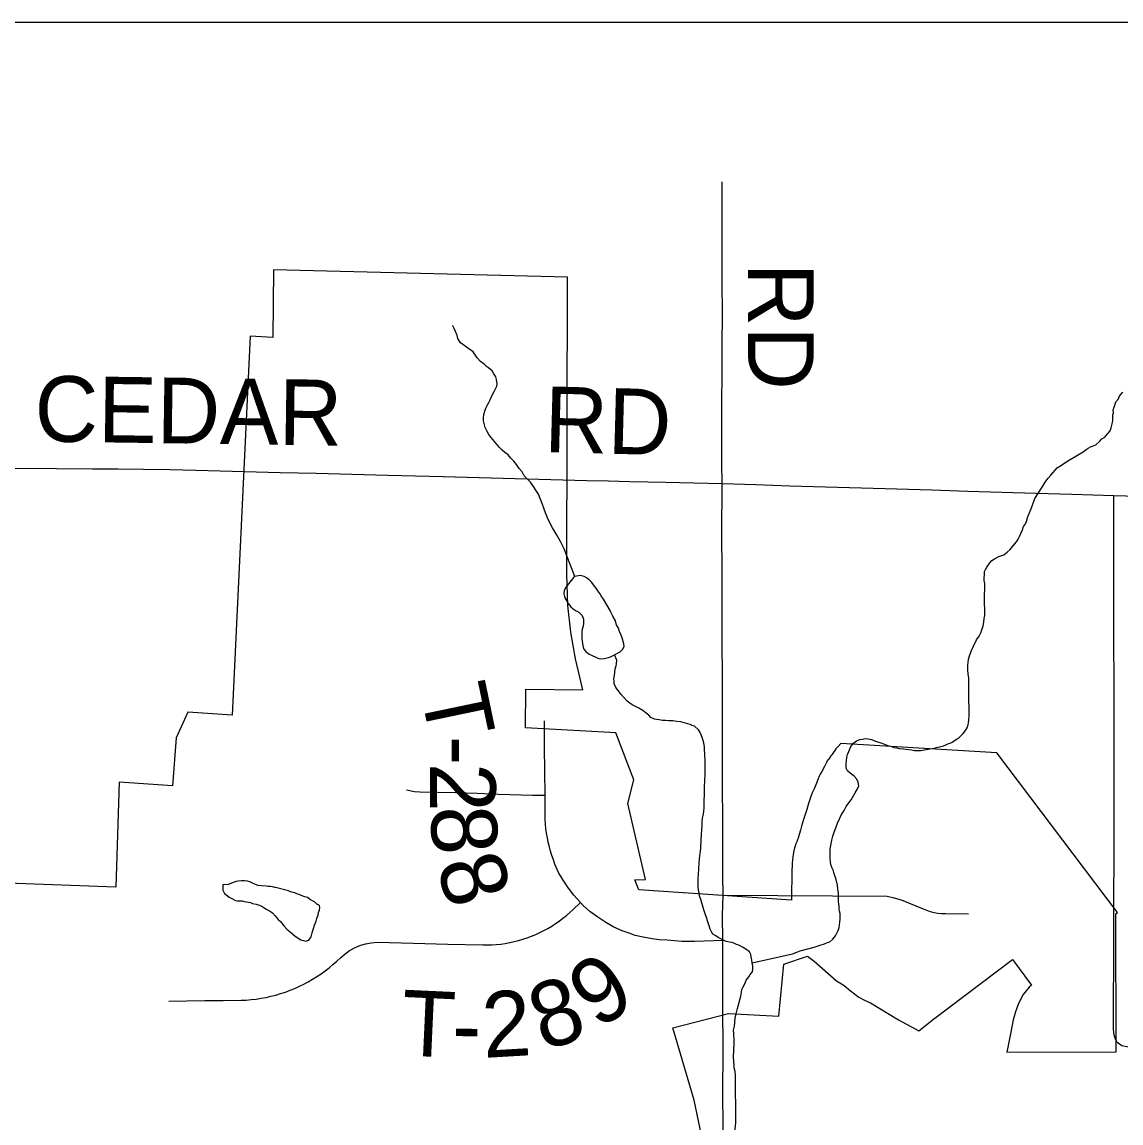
# Model space of a CAD drawing. Extents: x -11.4 to 84.1, y 11.1 to 59.
# Drawn here: x 26.686 to 27.637, y 46.596 to 47.548 of the extents above; entities that cross this region are included whole.
import ezdxf

# ---------------------------------------------------------------- set-up
doc = ezdxf.new("R2010")
doc.units = 0
for name, color, linetype in [('GM_X_Corporation', 7, 'Continuous'), ('GM_X_County_Road', 7, 'Continuous'), ('GM_X_Minor_Lake', 7, 'Continuous'), ('GM_X_Minor_River', 7, 'Continuous'), ('GM_X_Township_Road', 7, 'Continuous'), ('GM_X_Township_Road_Text', 7, 'Continuous'), ('SH_Data', 7, 'Continuous')]:
    doc.layers.add(name, color=color, linetype=linetype)

msp = doc.modelspace()

# ---------------------------------------------------------------- linework, layer by layer
at = {"layer": 'GM_X_Corporation'}
msp.add_lwpolyline([(27.27514, 46.58055), (27.2676, 46.61619), (27.24901, 46.67863), (27.29719, 46.69113), (27.3408, 46.68889), (27.34512, 46.73369), (27.36572, 46.74079), (27.37133, 46.73627), (27.39065, 46.71933), (27.39506, 46.71669), (27.39726, 46.71521), (27.4028, 46.71064), (27.40986, 46.70517), (27.41535, 46.70247), (27.42001, 46.70036), (27.44437, 46.68562), (27.46202, 46.67626), (27.47456, 46.6863), (27.54288, 46.73774), (27.55923, 46.71551), (27.55737, 46.71377), (27.5522, 46.7075), (27.54793, 46.69971), (27.54535, 46.69255), (27.54351, 46.6856), (27.54232, 46.67951), (27.54114, 46.67343), (27.53802, 46.65776), (27.63255, 46.65798), (27.63222, 46.77733), (27.63362, 46.77838), (27.52935, 46.91641), (27.39437, 46.92466), (27.39143, 46.92142), (27.39023, 46.91997), (27.38923, 46.91859), (27.38779, 46.91637), (27.3867, 46.91481), (27.38592, 46.91375), (27.38424, 46.91168), (27.38334, 46.91046), (27.38303, 46.90999), (27.3819, 46.90802), (27.38103, 46.90633), (27.38017, 46.90464), (27.37757, 46.89981), (27.37662, 46.89795), (27.37581, 46.89624), (27.37487, 46.89397), (27.37227, 46.88746), (27.37134, 46.88539), (27.36971, 46.88195), (27.36876, 46.87968), (27.36838, 46.87861), (27.36784, 46.877), (27.36706, 46.87447), (27.36653, 46.87261), (27.36507, 46.86755), (27.36219, 46.85875), (27.36036, 46.85297), (27.35942, 46.84969), (27.35838, 46.84586), (27.35741, 46.84259), (27.35703, 46.84152), (27.35627, 46.83958), (27.35573, 46.83835), (27.35548, 46.83774), (27.35523, 46.83712), (27.3548, 46.83587), (27.35443, 46.83441), (27.35386, 46.83182), (27.35327, 46.82845), (27.35296, 46.8262), (27.35291, 46.82601), (27.3527, 46.82432), (27.35239, 46.82093), (27.35223, 46.81809), (27.35213, 46.81563), (27.35176, 46.78907), (27.21972, 46.79809), (27.21617, 46.80655), (27.2255, 46.80683), (27.21031, 46.87256), (27.21544, 46.89314), (27.19972, 46.93371), (27.12166, 46.93816), (27.12189, 46.97164), (27.17133, 46.971), (27.16503, 46.99759), (27.16093, 47.02066), (27.15843, 47.04376), (27.1575, 47.0708), (27.158, 47.3276), (26.90368, 47.334), (26.90311, 47.27557), (26.88372, 47.27668), (26.86809, 46.94891), (26.82975, 46.95168), (26.8196, 46.92956), (26.81658, 46.88782), (26.77048, 46.89116), (26.76735, 46.80026), (26.46289, 46.81152)], dxfattribs=at)
at = {"layer": 'GM_X_County_Road'}
for points in [[(27.29244, 46.61478), (27.29256, 46.66641), (27.29247, 46.69032), (27.29239, 46.71422), (27.29251, 46.75429), (27.29212, 46.77588), (27.29269, 46.79339), (27.29251, 46.80989), (27.29233, 46.8264), (27.29226, 46.85747), (27.29218, 46.88854), (27.29211, 46.9196), (27.29203, 46.95067), (27.29196, 46.98174), (27.29188, 47.01281), (27.2918, 47.04388), (27.29173, 47.07429), (27.29165, 47.10471), (27.2917, 47.14943), (27.29157, 47.16728), (27.29145, 47.18513), (27.29162, 47.2162), (27.2918, 47.24726), (27.29193, 47.27063), (27.29206, 47.294), (27.29192, 47.32507), (27.29184, 47.34399), (27.29176, 47.36291), (27.29185, 47.39398), (27.29189, 47.41026)], [(27.293, 46.57827), (27.29265, 46.60103), (27.29244, 46.61478)]]:
    msp.add_lwpolyline(points, dxfattribs=at)
at = {"layer": 'GM_X_Minor_Lake'}
for points in [[(27.16357, 47.06836), (27.15665, 47.05964), (27.15516, 47.05659), (27.15481, 47.05392), (27.1556, 47.05165), (27.156, 47.04975), (27.15755, 47.04749), (27.15871, 47.04559), (27.16103, 47.04258), (27.16294, 47.04108), (27.16563, 47.0392), (27.16792, 47.03809), (27.17062, 47.03507), (27.17179, 47.03204), (27.17183, 47.02862), (27.17148, 47.02595), (27.17075, 47.02328), (27.1704, 47.02138), (27.17042, 47.01948), (27.17044, 47.0172), (27.17047, 47.0153), (27.17087, 47.01302), (27.1709, 47.01112), (27.1713, 47.00884), (27.17209, 47.00619), (27.17402, 47.00393), (27.17671, 47.00167), (27.17938, 47.00056), (27.18244, 46.99907), (27.18511, 46.99795), (27.18702, 46.99759), (27.19005, 46.998), (27.19347, 46.9988), (27.19536, 46.99958), (27.19876, 47.00113), (27.2014, 47.00268), (27.20367, 47.00384), (27.20555, 47.00576), (27.20704, 47.00844), (27.20663, 47.01072), (27.20543, 47.01603), (27.20426, 47.01868), (27.20309, 47.02133), (27.20229, 47.02436), (27.20036, 47.027), (27.19996, 47.02928), (27.19917, 47.03117), (27.19723, 47.03458), (27.19567, 47.03798), (27.19507, 47.03939)], [(27.19507, 47.03939), (27.18908, 47.04932), (27.18714, 47.05234), (27.18598, 47.05423), (27.18443, 47.0565), (27.18289, 47.05876), (27.18057, 47.06178), (27.17903, 47.06367), (27.17672, 47.06593), (27.17442, 47.0678), (27.1725, 47.06893), (27.16908, 47.06965), (27.16452, 47.06885), (27.16357, 47.06836)], [(26.90549, 46.80004), (26.90496, 46.80012), (26.90306, 46.80048), (26.90115, 46.80084), (26.89925, 46.80082), (26.89734, 46.80118), (26.89354, 46.80152), (26.89049, 46.80187), (26.88821, 46.80261), (26.88553, 46.80372), (26.88324, 46.80484), (26.88133, 46.80558), (26.87866, 46.80594), (26.876, 46.80591), (26.87335, 46.8055), (26.87145, 46.8051), (26.8688, 46.80432), (26.86691, 46.80354), (26.86464, 46.80275), (26.86008, 46.80233)], [(26.86008, 46.80233), (26.86013, 46.79777), (26.8613, 46.79474), (26.86361, 46.79324), (26.86552, 46.79174), (26.86782, 46.79062), (26.87088, 46.78875), (26.87279, 46.78839), (26.87468, 46.78841), (26.87658, 46.78843), (26.87849, 46.78806), (26.8804, 46.7877), (26.88383, 46.78698), (26.88573, 46.78624), (26.88879, 46.78551), (26.89222, 46.7844), (26.89451, 46.78328), (26.89758, 46.78141), (26.90025, 46.77992), (26.90294, 46.77804), (26.90525, 46.77541), (26.90794, 46.77239), (26.90987, 46.77051), (26.91295, 46.76674), (26.91526, 46.7641), (26.91833, 46.76185), (26.92025, 46.75997), (26.92256, 46.75809), (26.92754, 46.75472), (26.92982, 46.75436), (26.93173, 46.75362), (26.93438, 46.75441), (26.93625, 46.75747), (26.93735, 46.7609), (26.93771, 46.7628), (26.93845, 46.76471), (26.93918, 46.76738), (26.94066, 46.77082), (26.94139, 46.77311), (26.94249, 46.77654), (26.94285, 46.77844), (26.94358, 46.78035), (26.94394, 46.78264), (26.94354, 46.78453), (26.94124, 46.78565), (26.93932, 46.78753), (26.93588, 46.7894), (26.93319, 46.79127), (26.93091, 46.79201), (26.92785, 46.79312), (26.92594, 46.79386), (26.92403, 46.7946), (26.92212, 46.79534), (26.91945, 46.79608), (26.91678, 46.79719), (26.90549, 46.80004)]]:
    msp.add_lwpolyline(points, dxfattribs=at)
at = {"layer": 'GM_X_Minor_River'}
for points in [[(27.16452, 47.06885), (27.15512, 47.0927), (27.152, 47.09914), (27.14851, 47.10518), (27.14503, 47.11085), (27.14153, 47.11766), (27.13918, 47.12296), (27.13761, 47.12789), (27.13604, 47.13205), (27.13447, 47.13622), (27.1329, 47.14001), (27.13058, 47.14341), (27.12864, 47.14681), (27.12594, 47.15058), (27.12286, 47.15359), (27.12055, 47.15585), (27.11899, 47.15926), (27.1163, 47.16227), (27.11397, 47.16567), (27.11166, 47.16869), (27.10897, 47.17132), (27.10666, 47.17396), (27.10397, 47.17622), (27.10167, 47.17809), (27.09936, 47.18035), (27.09782, 47.18224), (27.09204, 47.18902), (27.09011, 47.19167), (27.08855, 47.19431), (27.08699, 47.19772), (27.08621, 47.19999), (27.08541, 47.20341), (27.08537, 47.20607), (27.08572, 47.20911), (27.08645, 47.21178), (27.08756, 47.21445), (27.08867, 47.21674), (27.08979, 47.21866), (27.09128, 47.22171), (27.09276, 47.22515), (27.09461, 47.22897), (27.0961, 47.23165), (27.09684, 47.23356), (27.0972, 47.23546), (27.09678, 47.23926), (27.09599, 47.24153), (27.09444, 47.24418), (27.09288, 47.24682), (27.08981, 47.24945), (27.0879, 47.25057), (27.08598, 47.25246), (27.08291, 47.25471), (27.07983, 47.2581), (27.07635, 47.26301), (27.07175, 47.26638), (27.0683, 47.26901), (27.06561, 47.27088), (27.06329, 47.27466), (27.0625, 47.27731), (27.06132, 47.28072), (27.06015, 47.28337), (27.05898, 47.28564), (27.05897, 47.28602)], [(27.63152, 47.21799), (27.63225, 47.21989), (27.6345, 47.22258), (27.63524, 47.22449), (27.63824, 47.22832)], [(27.49272, 46.92727), (27.49499, 46.92843), (27.49687, 46.92959), (27.49837, 46.93151), (27.50025, 46.93305), (27.50212, 46.93573), (27.50362, 46.93802), (27.50436, 46.93993), (27.50471, 46.94222), (27.50505, 46.94526), (27.5054, 46.94831), (27.50536, 46.95173), (27.50531, 46.95591), (27.50525, 46.96085), (27.5052, 46.9658), (27.50512, 46.97226), (27.50506, 46.9772), (27.50502, 46.981), (27.5046, 46.9848), (27.50418, 46.98784), (27.50415, 46.9905), (27.50413, 46.9924), (27.50448, 46.99468), (27.50483, 46.99735), (27.50593, 47.00116), (27.5074, 47.00498), (27.50926, 47.0088), (27.51186, 47.01415), (27.5141, 47.01721), (27.51559, 47.02027), (27.51669, 47.0237), (27.51742, 47.02637), (27.51814, 47.02942), (27.51849, 47.03246), (27.51884, 47.03513), (27.51881, 47.03741), (27.51868, 47.04843), (27.51864, 47.05185), (27.51861, 47.05452), (27.51896, 47.0568), (27.51893, 47.05984), (27.51889, 47.06288), (27.51848, 47.06554), (27.51846, 47.06782), (27.5188, 47.07049), (27.51877, 47.07315), (27.51951, 47.07506), (27.52063, 47.07697), (27.52325, 47.0808), (27.52512, 47.08271), (27.52739, 47.08426), (27.53117, 47.0862), (27.53533, 47.08776), (27.53834, 47.09007), (27.54098, 47.09238), (27.54323, 47.09506), (27.54622, 47.09889), (27.54772, 47.10119), (27.54883, 47.10348), (27.54994, 47.10615), (27.55143, 47.10921), (27.55253, 47.11226), (27.55403, 47.11456), (27.55514, 47.11723), (27.55586, 47.1199), (27.55735, 47.12334), (27.55883, 47.12677), (27.5603, 47.13059), (27.56214, 47.13631), (27.5655, 47.14129), (27.56848, 47.14626), (27.5711, 47.15047), (27.57372, 47.15392), (27.57597, 47.1566), (27.5816, 47.16274), (27.58386, 47.16428), (27.58688, 47.16622), (27.59065, 47.16892), (27.59632, 47.17201), (27.60047, 47.17471), (27.60387, 47.17665), (27.6065, 47.17858), (27.60839, 47.17974), (27.61028, 47.1809), (27.61217, 47.18167), (27.61482, 47.18284), (27.61821, 47.18554), (27.62008, 47.18784), (27.62272, 47.18938), (27.62535, 47.19245), (27.62722, 47.19475), (27.62833, 47.19742), (27.62869, 47.19971), (27.62942, 47.202), (27.62978, 47.2039), (27.62976, 47.2058), (27.62973, 47.20846), (27.63008, 47.21037), (27.63005, 47.21303), (27.63079, 47.21532), (27.63152, 47.21799)], [(27.2401, 46.94452), (27.23743, 46.94487), (27.23515, 46.94523), (27.23324, 46.94559), (27.23018, 46.94708), (27.22826, 46.94896), (27.22596, 46.95084), (27.22327, 46.95309), (27.21983, 46.95496), (27.21677, 46.95645), (27.21447, 46.95757), (27.21218, 46.95907), (27.20949, 46.96132), (27.20718, 46.96396), (27.20448, 46.96697), (27.20178, 46.97037), (27.19985, 46.97301), (27.19829, 46.97604), (27.19827, 46.97794), (27.19824, 46.9806), (27.19859, 46.98326), (27.19894, 46.98593), (27.19928, 46.98897), (27.20001, 46.99164), (27.20037, 46.99355), (27.20072, 46.99659), (27.19876, 47.00113)], [(27.30368, 46.59651), (27.30334, 46.63795), (27.30293, 46.64099), (27.30213, 46.64402), (27.30211, 46.6463), (27.30165, 46.65314), (27.30195, 46.65961), (27.30227, 46.66455), (27.30222, 46.66912), (27.30181, 46.67215), (27.30178, 46.67405), (27.30175, 46.67671), (27.30247, 46.68014), (27.30282, 46.68319), (27.30315, 46.68699), (27.30387, 46.6908), (27.30496, 46.69538), (27.30787, 46.70605), (27.30859, 46.70948), (27.30895, 46.71177), (27.30969, 46.71367), (27.31155, 46.71673), (27.31266, 46.71979), (27.3149, 46.72285), (27.31602, 46.72476), (27.3179, 46.72706), (27.31824, 46.72973), (27.31822, 46.73201), (27.3178, 46.73505), (27.31739, 46.73732), (27.31698, 46.73998), (27.31658, 46.74226), (27.31541, 46.74452), (27.31234, 46.74678), (27.31004, 46.74827), (27.30622, 46.75014), (27.30431, 46.75088), (27.3024, 46.75162), (27.30049, 46.75236), (27.29821, 46.75272), (27.29516, 46.75345), (27.29248, 46.75494), (27.29057, 46.75568), (27.28828, 46.7568), (27.28636, 46.7583), (27.28368, 46.7598), (27.28252, 46.76169), (27.28135, 46.76396), (27.28056, 46.76699), (27.27938, 46.7704), (27.27819, 46.77419), (27.27701, 46.77722), (27.27584, 46.78063), (27.27345, 46.78973), (27.27227, 46.79276), (27.27186, 46.79542), (27.27145, 46.79807), (27.27104, 46.80073), (27.271, 46.80415), (27.27096, 46.80795), (27.2713, 46.81138), (27.27162, 46.81595), (27.27194, 46.82165), (27.27263, 46.82736), (27.27332, 46.83383), (27.27361, 46.84106), (27.27393, 46.846), (27.27427, 46.84981), (27.27461, 46.85361), (27.27457, 46.85704), (27.27491, 46.86008), (27.27563, 46.86351), (27.27598, 46.86617), (27.27633, 46.86884), (27.2763, 46.87188), (27.27625, 46.87568), (27.27658, 46.87987), (27.2765, 46.88671), (27.27682, 46.89242), (27.27713, 46.89774), (27.27709, 46.90192), (27.27705, 46.90534), (27.27698, 46.91105), (27.27695, 46.91333), (27.27692, 46.91637), (27.27652, 46.91827), (27.27648, 46.92131), (27.27606, 46.92511), (27.27487, 46.9289), (27.2737, 46.93193), (27.27253, 46.93458), (27.27136, 46.93646), (27.26791, 46.93947), (27.266, 46.94021), (27.26409, 46.94096), (27.25608, 46.94316), (27.25265, 46.9435), (27.24922, 46.94423), (27.2458, 46.94419), (27.24276, 46.94454), (27.2401, 46.94452)], [(27.3178, 46.73505), (27.35269, 46.74262), (27.35647, 46.74418), (27.35912, 46.74534), (27.37125, 46.74851), (27.37655, 46.75008), (27.38034, 46.75126), (27.38299, 46.75243), (27.38488, 46.7532), (27.38751, 46.75551), (27.38976, 46.7582), (27.39087, 46.76049), (27.39199, 46.76278), (27.3931, 46.76545), (27.39343, 46.77002), (27.39378, 46.77268), (27.39374, 46.77534), (27.39372, 46.77763), (27.39332, 46.77952), (27.39291, 46.7818), (27.39288, 46.78408), (27.39246, 46.7875), (27.39242, 46.7913), (27.39237, 46.7951), (27.39195, 46.7989), (27.39153, 46.80194), (27.39034, 46.80687), (27.38954, 46.80952), (27.38876, 46.81179), (27.38797, 46.81445), (27.3868, 46.81672), (27.38601, 46.81899), (27.3856, 46.82165), (27.38517, 46.82582), (27.38513, 46.82963), (27.38509, 46.83305), (27.38581, 46.83648), (27.38652, 46.84105), (27.38762, 46.84448), (27.38872, 46.84791), (27.39019, 46.85173), (27.39167, 46.85555), (27.39315, 46.85936), (27.395, 46.86318), (27.39724, 46.86663), (27.39911, 46.87007), (27.40135, 46.87313), (27.40322, 46.87581), (27.40695, 46.88193), (27.40881, 46.88537), (27.40992, 46.88804), (27.4095, 46.89108), (27.40833, 46.89373), (27.40602, 46.89637), (27.40257, 46.89899), (27.40027, 46.90088), (27.3991, 46.90314), (27.39907, 46.90542), (27.39905, 46.90733), (27.39941, 46.90961), (27.39975, 46.91266), (27.4001, 46.91494), (27.40121, 46.91761), (27.40307, 46.92181), (27.40531, 46.92488), (27.40795, 46.92681), (27.41098, 46.92797), (27.41325, 46.92838), (27.41553, 46.92878), (27.4182, 46.92843), (27.42086, 46.92807), (27.4243, 46.92659), (27.42888, 46.92511), (27.43231, 46.92401), (27.43499, 46.92289), (27.43766, 46.92216), (27.44033, 46.92104), (27.44299, 46.92069), (27.4449, 46.92033), (27.44871, 46.91999), (27.45099, 46.91963), (27.45328, 46.91927), (27.45594, 46.91892), (27.45822, 46.91856), (27.46089, 46.91859), (27.46355, 46.91862), (27.47152, 46.91984), (27.47341, 46.92023), (27.47531, 46.92063), (27.4772, 46.92103), (27.481, 46.92183), (27.48327, 46.92261), (27.48516, 46.92339), (27.48705, 46.92417), (27.48894, 46.92495), (27.49083, 46.92573), (27.49272, 46.92727)], [(27.30202, 46.58102), (27.30368, 46.59651)]]:
    msp.add_lwpolyline(points, dxfattribs=at)
at = {"layer": 'GM_X_Township_Road'}
for points in [[(26.59374, 47.16259), (26.71623, 47.16224), (26.7473, 47.16205), (26.76932, 47.16191), (26.79135, 47.16178), (26.81406, 47.16137), (26.83677, 47.16095), (26.85763, 47.16029), (26.87848, 47.15964), (26.90954, 47.15889), (26.9406, 47.15813), (26.97167, 47.15738), (27.00273, 47.15662), (27.02665, 47.15604), (27.05058, 47.15546), (27.08163, 47.15461), (27.11269, 47.15375), (27.14374, 47.1529), (27.1748, 47.15205), (27.19337, 47.15154), (27.21194, 47.15103), (27.243, 47.15041), (27.26735, 47.14992), (27.2917, 47.14943)], [(27.2917, 47.14943), (27.32094, 47.14843), (27.35019, 47.14743), (27.38124, 47.1465), (27.4123, 47.14557), (27.44275, 47.14465), (27.47319, 47.14374), (27.50425, 47.14281), (27.53374, 47.14193), (27.56324, 47.14105), (27.59429, 47.1401), (27.61234, 47.13955), (27.63039, 47.139), (27.66144, 47.13797)], [(27.63337, 46.66622), (27.63201, 46.66901), (27.63087, 46.67226), (27.63051, 46.67491), (27.6302, 46.67729), (27.63028, 46.70309), (27.63038, 46.73319), (27.63047, 46.76329), (27.63062, 46.79436), (27.63075, 46.82292), (27.63088, 46.85148), (27.63039, 47.139)], [(27.29251, 46.75429), (27.28458, 46.75397), (27.26795, 46.75328), (27.25686, 46.75346), (27.24414, 46.75441), (27.23733, 46.75485), (27.23116, 46.75554), (27.22348, 46.75699), (27.21667, 46.75863), (27.21126, 46.76058), (27.20521, 46.76272), (27.19822, 46.76581), (27.1911, 46.76984), (27.18423, 46.77438), (27.1775, 46.77929), (27.17157, 46.78452), (27.16918, 46.78721), (27.16357, 46.79352), (27.15891, 46.79951), (27.15419, 46.80625), (27.15022, 46.81305), (27.1472, 46.8201), (27.14601, 46.82395), (27.14464, 46.82768), (27.14346, 46.83145), (27.14237, 46.83527), (27.14143, 46.83913), (27.14062, 46.84301), (27.13996, 46.84692), (27.13944, 46.85086), (27.13906, 46.85481), (27.13883, 46.85877), (27.13873, 46.86274), (27.13888, 46.87982), (27.13857, 46.90076), (27.13826, 46.9217), (27.13803, 46.94427)], [(27.01895, 46.88435), (27.02566, 46.88297), (27.03032, 46.88271), (27.06134, 46.88215), (27.0799, 46.88151), (27.09845, 46.88087), (27.12774, 46.87985), (27.13888, 46.87982)], [(27.29269, 46.79339), (27.4344, 46.79248), (27.43943, 46.79128), (27.44662, 46.7893), (27.46557, 46.78159), (27.4686, 46.78035), (27.47178, 46.77933), (27.475, 46.77853), (27.47822, 46.77798), (27.48153, 46.77763), (27.48485, 46.77752), (27.50469, 46.77732)], [(26.9713, 46.74644), (26.97394, 46.74791), (26.97859, 46.74988), (26.98342, 46.75134), (26.98839, 46.75229), (26.99342, 46.7527), (27.02448, 46.75194), (27.05462, 46.75119), (27.08476, 46.75045), (27.09259, 46.75054), (27.09651, 46.75078), (27.1004, 46.75119), (27.10429, 46.75173), (27.10817, 46.7524), (27.11201, 46.75323), (27.1158, 46.75419), (27.11955, 46.75528), (27.12329, 46.75652), (27.12698, 46.75788), (27.13058, 46.75938), (27.13414, 46.761), (27.13765, 46.76276), (27.14111, 46.76465), (27.14447, 46.76666), (27.14779, 46.76878), (27.15096, 46.77103), (27.1541, 46.7734), (27.15717, 46.77587), (27.16011, 46.77845), (27.16296, 46.78114), (27.16918, 46.78721)], [(26.81338, 46.70189), (26.84445, 46.70221), (26.86017, 46.70237), (26.8759, 46.70252), (26.88021, 46.70273), (26.88456, 46.70311), (26.88888, 46.70362), (26.89314, 46.70427), (26.89741, 46.70507), (26.90163, 46.70601), (26.90584, 46.7071), (26.91001, 46.70833), (26.91413, 46.70969), (26.91816, 46.7112), (26.92219, 46.71284), (26.92617, 46.7146), (26.93005, 46.71651), (26.93389, 46.71854), (26.93764, 46.72071), (26.94134, 46.72301), (26.94494, 46.72541), (26.94845, 46.72794), (26.95186, 46.7306), (26.95522, 46.73335), (26.95844, 46.73623), (26.96162, 46.7392), (26.96541, 46.74254), (26.96954, 46.74545), (26.9713, 46.74644)], [(27.63337, 46.66622), (27.63746, 46.66352), (27.64311, 46.66237), (27.67418, 46.66258), (27.70524, 46.66279), (27.72956, 46.66295), (27.75388, 46.66312), (27.75735, 46.66451)]]:
    msp.add_lwpolyline(points, dxfattribs=at)
at = {"layer": 'SH_Data'}
msp.add_line((26.16529, 47.54828), (33.16529, 47.54828), dxfattribs=at)

# ---------------------------------------------------------------- texts
at = {"layer": 'GM_X_Township_Road_Text'}
for s, height, rotation, p in [('RD', 0.056818, 270, (27.31421, 47.34005)), ('CEDAR', 0.056818, 359.1903, (26.69691, 47.18574)), ('RD', 0.056818, 358.51749, (27.13745, 47.17655)), ('T', 0.05682, 281.80413, (27.03068, 46.96965)), ('-', 0.05682, 270.08588, (27.03905, 46.93109)), ('2', 0.05682, 270.14352, (27.03909, 46.9077)), ('8', 0.05682, 273.29492, (27.03928, 46.8693)), ('8', 0.05682, 287.27924, (27.04399, 46.81951)), ('9', 0.05682, 33.60755, (27.18434, 46.67658)), ('8', 0.05682, 19.35509, (27.13756, 46.65813)), ('T', 0.05682, 357.37194, (27.01346, 46.65495)), ('2', 0.05682, 3.32159, (27.08567, 46.6527)), ('-', 0.05682, 359.16464, (27.05785, 46.65294))]:
    msp.add_text(s, height=height, rotation=rotation, dxfattribs=at).set_placement(p)

doc.saveas('drawing.dxf')
